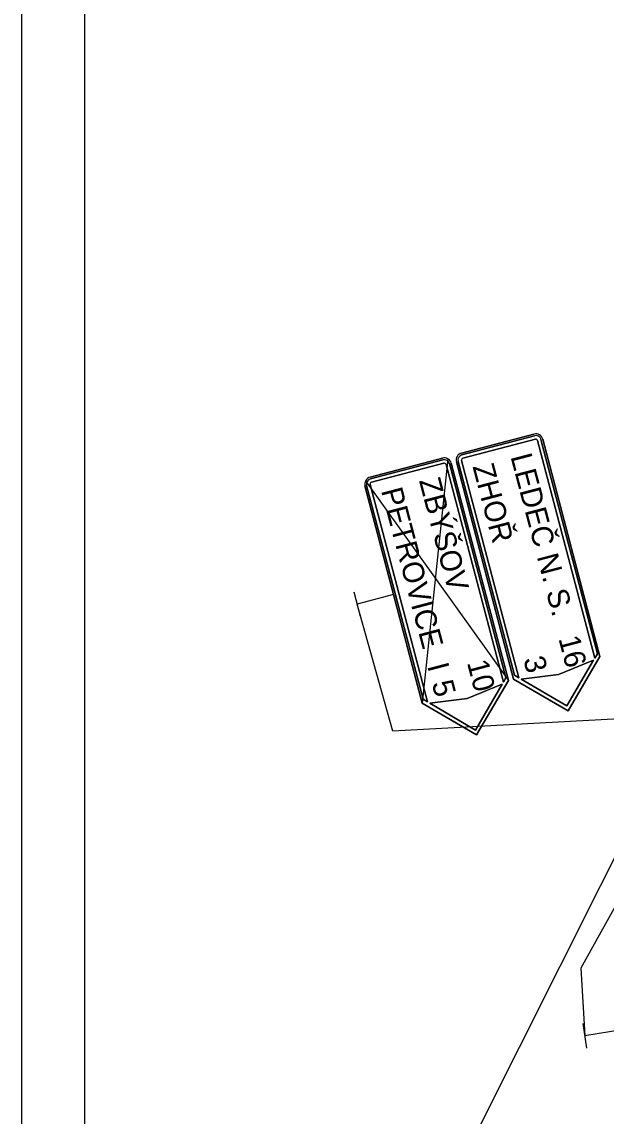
# Model space of a CAD drawing. Extents: x -688893 to -679983, y -1088371 to -1075771.
# Drawn here: x -688893 to -687501, y -1079697 to -1077085 of the extents above; entities that cross this region are included whole.
import ezdxf

# ---------------------------------------------------------------- set-up
doc = ezdxf.new("R2010")
doc.units = 0
for name, color, linetype in [('ramecek', 7, 'Continuous'), ('S SDZ', 7, 'Continuous'), ('S SDZ plochy', 7, 'Continuous'), ('S SDZ symbol', 7, 'Continuous'), ('SDZ', 7, 'Continuous')]:
    doc.layers.add(name, color=color, linetype=linetype)

msp = doc.modelspace()

# ---------------------------------------------------------------- linework, layer by layer
at = {"layer": 'ramecek'}
for points in [[(-679983.4, -1075770.7), (-679983.4, -1088370.7), (-688893.4, -1088370.7), (-688893.4, -1075770.7)], [(-680133.4, -1076070.7), (-680133.4, -1088220.7), (-688743.4, -1088220.7), (-688743.4, -1076070.7)]]:
    msp.add_lwpolyline(points, close=True, dxfattribs=at)
at = {"layer": 'S SDZ'}
for p, q in [((-687845.3, -1078114), (-687672.5, -1078068.6)), ((-687844.2, -1078118.2), (-687671.4, -1078072.7)), ((-687669.2, -1078080.9), (-687842.1, -1078126.4)), ((-687664, -1078084), (-687527.4, -1078603.3)), ((-687655.8, -1078081.8), (-687521.3, -1078592.9)), ((-687651.7, -1078080.7), (-687515.3, -1078599.3)), ((-688063.4, -1078171.4), (-687890.6, -1078126)), ((-688062.4, -1078175.5), (-687889.5, -1078130.1)), ((-687887.3, -1078138.3), (-688060.2, -1078183.8)), ((-687873.9, -1078139.2), (-687739.5, -1078650.3)), ((-687869.8, -1078138.1), (-687733.4, -1078656.6)), ((-687721, -1078653.4), (-687857.5, -1078134.8)), ((-687719, -1078644.4), (-687853.3, -1078133.8)), ((-687708.6, -1078650.5), (-687845.1, -1078131.6)), ((-687882.1, -1078141.3), (-687745.5, -1078660.7)), ((-687939.2, -1078710.8), (-688075.6, -1078192.2)), ((-687937.1, -1078701.8), (-688071.5, -1078191.1)), ((-687926.7, -1078707.9), (-688063.2, -1078189)), ((-687613.8, -1078642.8), (-687530.4, -1078608.5)), ((-687530.4, -1078608.5), (-687594.1, -1078717.7)), ((-687515.3, -1078599.3), (-687591.1, -1078729.2)), ((-687521.3, -1078592.9), (-687527.4, -1078603.3)), ((-687733.4, -1078656.6), (-687809.2, -1078786.6)), ((-687739.5, -1078650.3), (-687745.5, -1078660.7)), ((-687591.1, -1078729.2), (-687721, -1078653.4)), ((-687708.6, -1078650.5), (-687719, -1078644.4)), ((-687702.9, -1078653.9), (-687613.8, -1078642.8)), ((-687594.1, -1078717.7), (-687702.9, -1078653.9)), ((-687832, -1078700.2), (-687748.6, -1078665.9)), ((-687748.6, -1078665.9), (-687812.2, -1078775.1)), ((-687809.2, -1078786.6), (-687939.2, -1078710.8)), ((-687926.7, -1078707.9), (-687937.1, -1078701.8)), ((-687921, -1078711.3), (-687832, -1078700.2)), ((-687812.2, -1078775.1), (-687921, -1078711.3))]:
    msp.add_line(p, q, dxfattribs=at)
for centre, radius, start, end in [((-687668.1, -1078085), 17, 14.7382, 104.7382), ((-687668.1, -1078085), 12.8, 14.7382, 104.7382), ((-687668.1, -1078085), 4.26, 14.7382, 104.7382), ((-687841, -1078130.5), 17, 104.7382, 194.7382), ((-687886.3, -1078142.4), 17, 14.7382, 104.7382), ((-687886.3, -1078142.4), 12.8, 14.7382, 104.7382), ((-687886.3, -1078142.4), 4.26, 14.7382, 104.7382), ((-687841, -1078130.5), 12.8, 104.7382, 194.7382), ((-687841, -1078130.5), 4.26, 104.7382, 194.7382), ((-688059.1, -1078187.9), 17, 104.7382, 194.7382), ((-688059.1, -1078187.9), 12.8, 104.7382, 194.7382), ((-688059.1, -1078187.9), 4.26, 104.7382, 194.7382)]:
    msp.add_arc(centre, radius, start, end, dxfattribs=at)
at = {"layer": 'S SDZ plochy'}
for p, q in [((-687672.5, -1078068.6), (-687845.3, -1078114)), ((-687844.2, -1078118.2), (-687671.4, -1078072.7)), ((-687671.4, -1078072.7), (-687844.2, -1078118.2)), ((-687669.2, -1078080.9), (-687842.1, -1078126.4)), ((-687842.1, -1078126.4), (-687669.2, -1078080.9)), ((-687527.4, -1078603.3), (-687664, -1078084)), ((-687664, -1078084), (-687527.4, -1078603.3)), ((-687655.8, -1078081.8), (-687521.3, -1078592.9)), ((-687521.3, -1078592.9), (-687655.8, -1078081.8)), ((-687515.3, -1078599.3), (-687651.7, -1078080.7)), ((-687890.6, -1078126), (-688063.4, -1078171.4)), ((-688062.4, -1078175.5), (-687889.5, -1078130.1)), ((-687889.5, -1078130.1), (-688062.4, -1078175.5)), ((-687887.3, -1078138.3), (-688060.2, -1078183.8)), ((-688060.2, -1078183.8), (-687887.3, -1078138.3)), ((-687873.9, -1078139.2), (-687739.5, -1078650.3)), ((-687739.5, -1078650.3), (-687873.9, -1078139.2)), ((-687733.4, -1078656.6), (-687869.8, -1078138.1)), ((-687857.5, -1078134.8), (-687721, -1078653.4)), ((-687719, -1078644.4), (-687853.3, -1078133.8)), ((-687853.3, -1078133.8), (-687719, -1078644.4)), ((-687845.1, -1078131.6), (-687708.6, -1078650.5)), ((-687708.6, -1078650.5), (-687845.1, -1078131.6)), ((-687745.5, -1078660.7), (-687882.1, -1078141.3)), ((-687882.1, -1078141.3), (-687745.5, -1078660.7)), ((-688075.6, -1078192.2), (-687939.2, -1078710.8)), ((-687937.1, -1078701.8), (-688071.5, -1078191.1)), ((-688071.5, -1078191.1), (-687937.1, -1078701.8)), ((-688063.2, -1078189), (-687926.7, -1078707.9)), ((-687926.7, -1078707.9), (-688063.2, -1078189)), ((-687530.4, -1078608.5), (-687613.8, -1078642.8)), ((-687613.8, -1078642.8), (-687530.4, -1078608.5)), ((-687594.1, -1078717.7), (-687530.4, -1078608.5)), ((-687530.4, -1078608.5), (-687594.1, -1078717.7)), ((-687591.1, -1078729.2), (-687515.3, -1078599.3)), ((-687521.3, -1078592.9), (-687527.4, -1078603.3)), ((-687527.4, -1078603.3), (-687521.3, -1078592.9)), ((-687809.2, -1078786.6), (-687733.4, -1078656.6)), ((-687739.5, -1078650.3), (-687745.5, -1078660.7)), ((-687745.5, -1078660.7), (-687739.5, -1078650.3)), ((-687721, -1078653.4), (-687591.1, -1078729.2)), ((-687708.6, -1078650.5), (-687719, -1078644.4)), ((-687719, -1078644.4), (-687708.6, -1078650.5)), ((-687613.8, -1078642.8), (-687702.9, -1078653.9)), ((-687702.9, -1078653.9), (-687613.8, -1078642.8)), ((-687702.9, -1078653.9), (-687594.1, -1078717.7)), ((-687594.1, -1078717.7), (-687702.9, -1078653.9)), ((-687748.6, -1078665.9), (-687832, -1078700.2)), ((-687832, -1078700.2), (-687748.6, -1078665.9)), ((-687812.2, -1078775.1), (-687748.6, -1078665.9)), ((-687748.6, -1078665.9), (-687812.2, -1078775.1)), ((-687939.2, -1078710.8), (-687809.2, -1078786.6)), ((-687926.7, -1078707.9), (-687937.1, -1078701.8)), ((-687937.1, -1078701.8), (-687926.7, -1078707.9)), ((-687832, -1078700.2), (-687921, -1078711.3)), ((-687921, -1078711.3), (-687832, -1078700.2)), ((-687921, -1078711.3), (-687812.2, -1078775.1)), ((-687812.2, -1078775.1), (-687921, -1078711.3))]:
    msp.add_line(p, q, dxfattribs=at)
for centre, radius, start, end in [((-687668.1, -1078085), 17, 14.7382, 104.7382), ((-687668.1, -1078085), 12.8, 14.7382, 104.7382), ((-687668.1, -1078085), 12.8, 14.7382, 104.7382), ((-687668.1, -1078085), 4.26, 14.7382, 104.7382), ((-687668.1, -1078085), 4.26, 14.7382, 104.7382), ((-687841, -1078130.5), 17, 104.7382, 194.7382), ((-687886.3, -1078142.4), 17, 14.7382, 104.7382), ((-687886.3, -1078142.4), 12.8, 14.7382, 104.7382), ((-687886.3, -1078142.4), 12.8, 14.7382, 104.7382), ((-687886.3, -1078142.4), 4.26, 14.7382, 104.7382), ((-687886.3, -1078142.4), 4.26, 14.7382, 104.7382), ((-687841, -1078130.5), 12.8, 104.7382, 194.7382), ((-687841, -1078130.5), 12.8, 104.7382, 194.7382), ((-687841, -1078130.5), 4.26, 104.7382, 194.7382), ((-687841, -1078130.5), 4.26, 104.7382, 194.7382), ((-688059.1, -1078187.9), 17, 104.7382, 194.7382), ((-688059.1, -1078187.9), 12.8, 104.7382, 194.7382), ((-688059.1, -1078187.9), 12.8, 104.7382, 194.7382), ((-688059.1, -1078187.9), 4.26, 104.7382, 194.7382), ((-688059.1, -1078187.9), 4.26, 104.7382, 194.7382)]:
    msp.add_arc(centre, radius, start, end, dxfattribs=at)
at = {"layer": 'SDZ'}
for p, q in [((-687877.7, -1078127.7), (-687939.2, -1078710.8)), ((-688074.3, -1078180.2), (-687733.4, -1078656.6)), ((-688102, -1078445.4), (-688086.8, -1078503.4)), ((-688007.4, -1078451.5), (-688094.4, -1078474.4)), ((-687556.2, -1079475.3), (-687547, -1079534.6)), ((-687462.7, -1079491.1), (-687551.6, -1079505))]:
    msp.add_line(p, q, dxfattribs=at)
for points in [[(-687161.6, -1078731.6), (-688008.9, -1078777.5), (-688094.4, -1078474.4)], [(-687320.5, -1078761.1), (-687804.8, -1079726.1), (-687758.7, -1079941.2)], [(-687233.2, -1078753.7), (-687560.7, -1079343.2), (-687551.6, -1079505)]]:
    msp.add_lwpolyline(points, dxfattribs=at)

# ---------------------------------------------------------------- texts
at = {"layer": 'S SDZ symbol'}
for s, height, p in [('ZHOŘ', 51.07, (-687819.3, -1078146)), ('LEDEČ N. S.', 51.067, (-687728.8, -1078122.2)), ('ZBÝŠOV', 51.07, (-687946.9, -1078179.6)), ('PETROVICE  I', 51.067, (-688037.4, -1078203.4)), ('16', 51.07, (-687614.5, -1078556.6)), ('10', 51.07, (-687832.6, -1078614.1)), ('3', 51.1, (-687698.3, -1078606)), ('5', 51.1, (-687916.5, -1078663.1))]:
    msp.add_text(s, height=height, rotation=284.7382, dxfattribs=at).set_placement(p)

doc.saveas('drawing.dxf')
